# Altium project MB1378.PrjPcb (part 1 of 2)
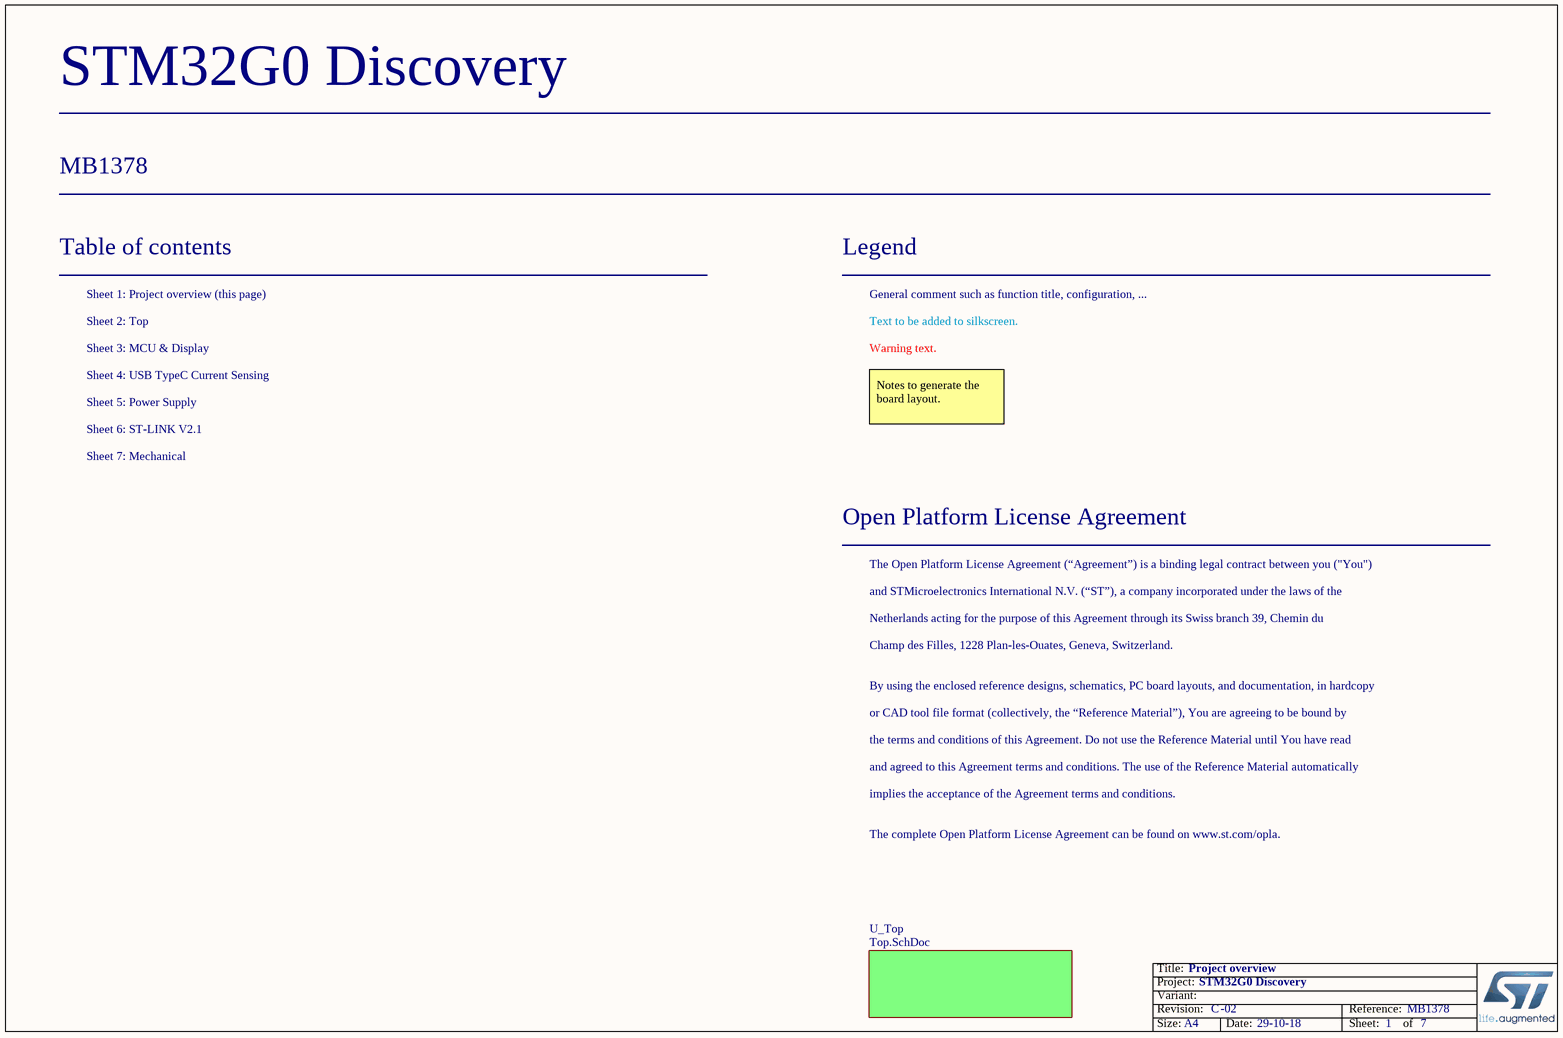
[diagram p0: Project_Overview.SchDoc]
Board_Reference: MB1378; Board_PCB_Revision: C; Board_Name: STM32G0 Discovery; Board_Document_Date: 29-10-18; Board_Assembly_Revision: 02
7 sheets, 200 parts. Net scope: flat (ports and power ports of the same name join across sheets).
Board file: MB1378.PcbDoc
Sheets:
  Project_Overview.SchDoc
    U_Top = Top.SchDoc
      USB Type C = USB_typeC_CurrentSensing.SchDoc
      ST-LINK v2.1 = ST_LINK_V2_1.SchDoc
      STM32G0 MCU and display = MCU_Display.SchDoc
      U_Power_Supply = Power_Supply.SchDoc
      U_Mechanical = Mechanical.SchDoc

## Sheet Project_Overview.SchDoc: Project overview
size A4; Date: Not used; ApprovedBy: Not used; CheckedBy: Not used; Author: Not used; CompanyName: STMicroelectronics; DrawnBy: Not used; Engineer: Not used; Organization: Not used; Address1: Not used; Address2: Not used; Address3: Not used; Address4: Not used; DocumentNumber: 1; Revision: Not used; SheetNumber: 1; SheetTotal: 7

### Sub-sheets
U_Top = Top.SchDoc: no entries

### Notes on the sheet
- Table of contents
- Sheet 1: Project overview (this page)
- Legend
- General comment such as function title, configuration, ...
- Sheet 2: Top
- Sheet 3: MCU & Display
- Sheet 4: USB TypeC Current Sensing
- Text to be added to silkscreen.
- Warning text.
- Sheet 5: Power Supply
- Sheet 6: ST-LINK V2.1
- Notes to generate the board layout.
- Sheet 7: Mechanical
- Open Platform License Agreement
- The Open Platform License Agreement (“Agreement”) is a binding legal contract between you ("You")
- and STMicroelectronics International N.V. (“ST”), a company incorporated under the laws of the
- Netherlands acting for the purpose of this Agreement through its Swiss branch 39, Chemin du
- Champ des Filles, 1228 Plan-les-Ouates, Geneva, Switzerland.
- By using the enclosed reference designs, schematics, PC board layouts, and documentation, in hardcopy
- or CAD tool file format (collectively, the “Reference Material”), You are agreeing to be bound by
- the terms and conditions of this Agreement. Do not use the Reference Material until You have read
- and agreed to this Agreement terms and conditions. The use of the Reference Material automatically
- implies the acceptance of the Agreement terms and conditions.
- The complete Open Platform License Agreement can be found on www.st.com/opla.

## Sheet Top.SchDoc: Top
size A4; Date: Not used; ApprovedBy: Not used; CheckedBy: Not used; Author: Not used; CompanyName: STMicroelectronics; DrawnBy: Not used; Engineer: Not used; Organization: Not used; Address1: Not used; Address2: Not used; Address3: Not used; Address4: Not used; DocumentNumber: 2; Revision: Not used; SheetNumber: 2; SheetTotal: 7
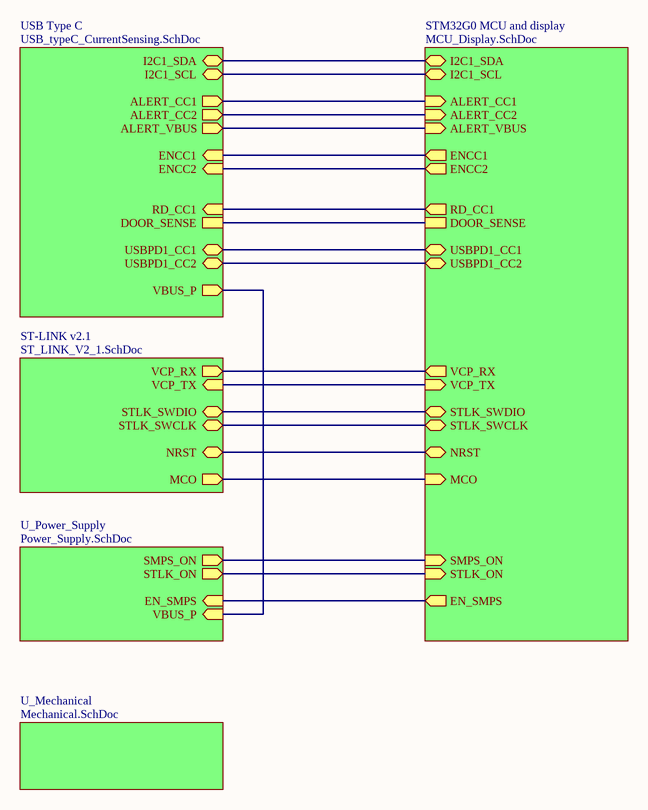
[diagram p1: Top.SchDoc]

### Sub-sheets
ST-LINK v2.1 = ST_LINK_V2_1.SchDoc: NRST (bidir), VCP_RX (out), VCP_TX (in), STLK_SWDIO (bidir), STLK_SWCLK (bidir), MCO (out)
STM32G0 MCU and display = MCU_Display.SchDoc: I2C1_SCL (bidir), I2C1_SDA (bidir), STLK_SWDIO (bidir), STLK_SWCLK (bidir), VCP_RX (out), VCP_TX (in), USBPD1_CC2 (bidir), USBPD1_CC1 (bidir), ENCC2 (out), ENCC1 (out), RD_CC1 (out), ALERT_CC1 (in), ALERT_CC2 (in), ALERT_VBUS (in), EN_SMPS (out), NRST (bidir), MCO (in), SMPS_ON (in), STLK_ON (in), DOOR_SENSE
U_Mechanical = Mechanical.SchDoc: no entries
U_Power_Supply = Power_Supply.SchDoc: SMPS_ON (out), STLK_ON (out), EN_SMPS (in), VBUS_P (in)
USB Type C = USB_typeC_CurrentSensing.SchDoc: I2C1_SDA (bidir), I2C1_SCL (bidir), ALERT_CC1 (out), ALERT_CC2 (out), ALERT_VBUS (out), ENCC2 (in), ENCC1 (in), USBPD1_CC2 (bidir), USBPD1_CC1 (bidir), RD_CC1 (in), VBUS_P (out), DOOR_SENSE

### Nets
(unnamed): sheet USB Type C/I2C1_SDA, sheet STM32G0 MCU and display/I2C1_SDA
(unnamed): sheet USB Type C/I2C1_SCL, sheet STM32G0 MCU and display/I2C1_SCL  [a separate net that carries the same name]
(unnamed): sheet USB Type C/ALERT_CC1, sheet STM32G0 MCU and display/ALERT_CC1  [a separate net that carries the same name]
(unnamed): sheet USB Type C/ALERT_CC2, sheet STM32G0 MCU and display/ALERT_CC2  [a separate net that carries the same name]
(unnamed): sheet USB Type C/ALERT_VBUS, sheet STM32G0 MCU and display/ALERT_VBUS  [a separate net that carries the same name]
(unnamed): sheet USB Type C/ENCC2, sheet STM32G0 MCU and display/ENCC2  [a separate net that carries the same name]
(unnamed): sheet USB Type C/ENCC1, sheet STM32G0 MCU and display/ENCC1  [a separate net that carries the same name]
(unnamed): sheet USB Type C/USBPD1_CC2, sheet STM32G0 MCU and display/USBPD1_CC2  [a separate net that carries the same name]
(unnamed): sheet USB Type C/USBPD1_CC1, sheet STM32G0 MCU and display/USBPD1_CC1  [a separate net that carries the same name]
(unnamed): sheet USB Type C/RD_CC1, sheet STM32G0 MCU and display/RD_CC1  [a separate net that carries the same name]
(unnamed): sheet USB Type C/VBUS_P, sheet U_Power_Supply/VBUS_P  [a separate net that carries the same name]
(unnamed): sheet USB Type C/DOOR_SENSE, sheet STM32G0 MCU and display/DOOR_SENSE  [a separate net that carries the same name]
(unnamed): sheet ST-LINK v2.1/NRST, sheet STM32G0 MCU and display/NRST  [a separate net that carries the same name]
(unnamed): sheet ST-LINK v2.1/VCP_RX, sheet STM32G0 MCU and display/VCP_RX  [a separate net that carries the same name]
(unnamed): sheet ST-LINK v2.1/VCP_TX, sheet STM32G0 MCU and display/VCP_TX  [a separate net that carries the same name]
(unnamed): sheet ST-LINK v2.1/STLK_SWDIO, sheet STM32G0 MCU and display/STLK_SWDIO  [a separate net that carries the same name]
(unnamed): sheet ST-LINK v2.1/STLK_SWCLK, sheet STM32G0 MCU and display/STLK_SWCLK  [a separate net that carries the same name]
(unnamed): sheet ST-LINK v2.1/MCO, sheet STM32G0 MCU and display/MCO  [a separate net that carries the same name]
(unnamed): sheet STM32G0 MCU and display/EN_SMPS, sheet U_Power_Supply/EN_SMPS  [a separate net that carries the same name]
(unnamed): sheet STM32G0 MCU and display/SMPS_ON, sheet U_Power_Supply/SMPS_ON  [a separate net that carries the same name]
(unnamed): sheet STM32G0 MCU and display/STLK_ON, sheet U_Power_Supply/STLK_ON  [a separate net that carries the same name]

## Sheet USB_typeC_CurrentSensing.SchDoc: USB TypeC Current Sensing
size A4; Date: Not used; ApprovedBy: Not used; CheckedBy: Not used; Author: Not used; CompanyName: STMicroelectronics; DrawnBy: Not used; Engineer: Not used; Organization: Not used; Address1: Not used; Address2: Not used; Address3: Not used; Address4: Not used; DocumentNumber: 4; Revision: Not used; SheetNumber: 4; SheetTotal: 7
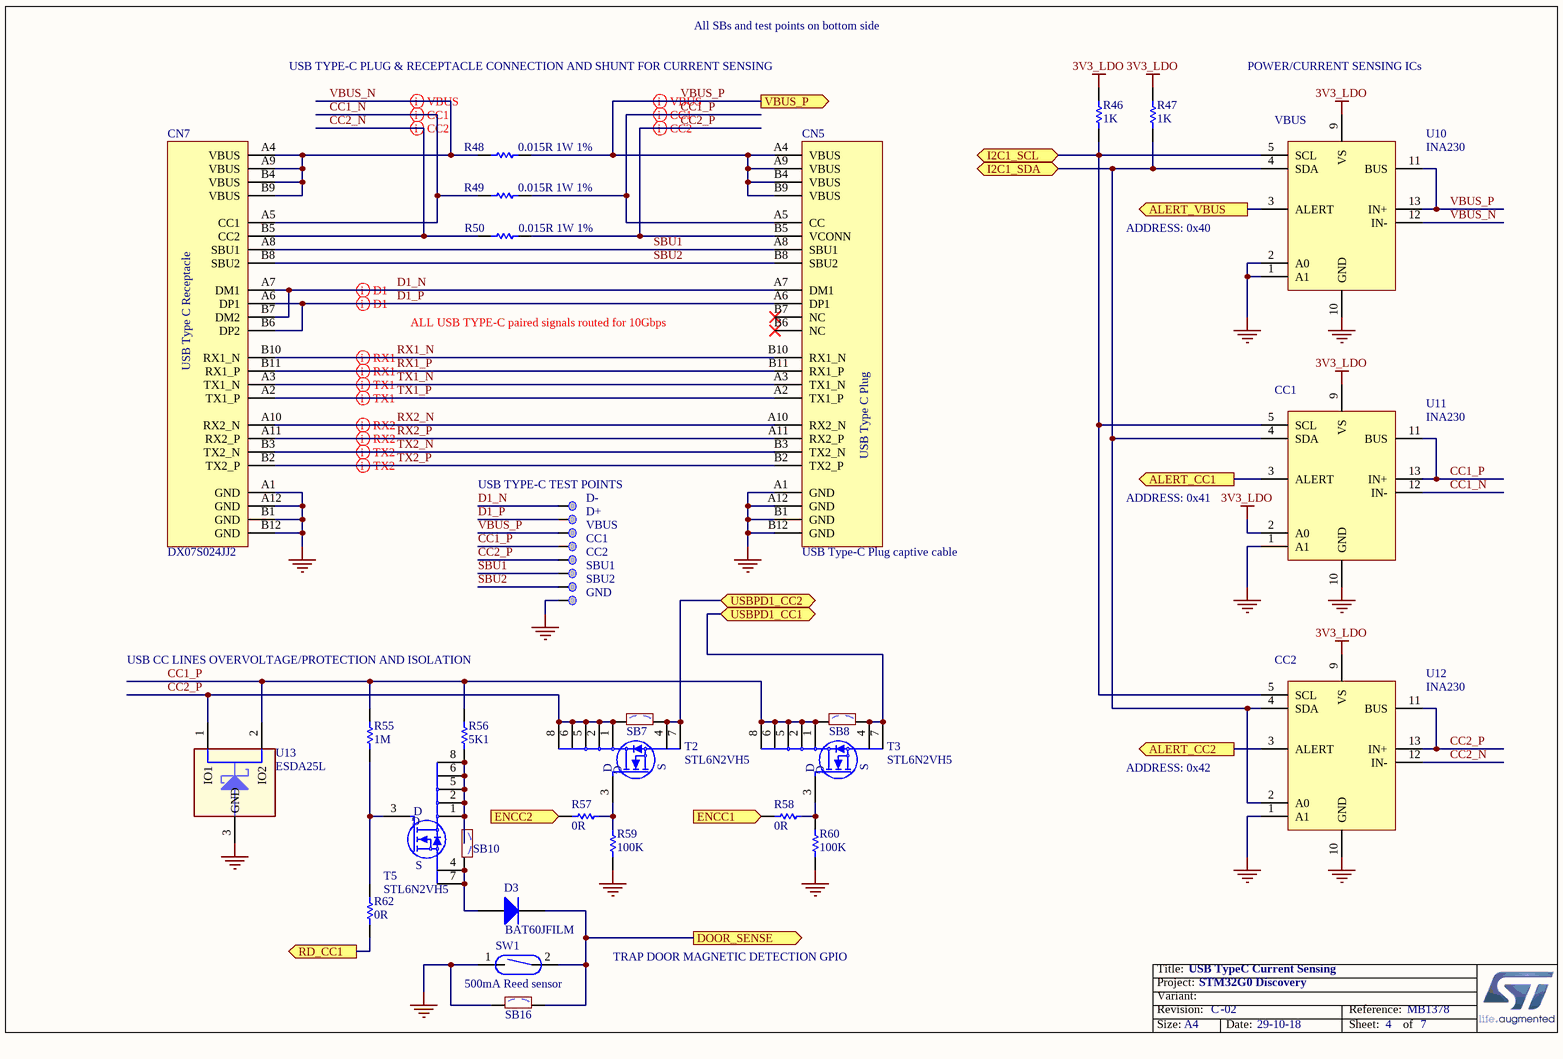
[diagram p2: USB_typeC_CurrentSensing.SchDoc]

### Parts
CC1  Test Point  [TP_SMD_2MM]  (value not drawn)  (no BOM)
CC2  Test Point  [TP_SMD_2MM]  (value not drawn)  (no BOM)
CN5  value USB Type-C Plug captive cable  (hidden comment: USB_TypeC_Plug_DX07P024MJ1)
CN7  value DX07S024JJ2  [CO_JAE_DX07S024JJ2]  (hidden comment: ​Footprint CO_JAE_DX07S024JJ2)
D3  value BAT60JFILM  [DIO_SOD323]
D+  Test Point  [TP_SMD_2MM]  (value not drawn)  (no BOM)
D-  Test Point  [TP_SMD_2MM]  (value not drawn)  (no BOM)
GND  Test Point  [TP_SMD_2MM]  (value not drawn)  (no BOM)
R46  value 1K  [R0603]  (hidden comment: Resistor)
R47  value 1K  [R0603]  (hidden comment: Resistor)
R48  value 0.015R 1W 1%  [RESC3216X06N]  (hidden comment: ​Footprint RESC3216X06N)
R49  value 0.015R 1W 1%  [RESC3216X06N]  (hidden comment: ​Footprint RESC3216X06N)
R50  value 0.015R 1W 1%  [RESC3216X06N]  (hidden comment: ​Footprint RESC3216X06N)
R55  value 1M  [R0603]
R56  value 5K1  [R0402]
R57  value 0R  [R0603]  (hidden comment: Resistor)
R58  value 0R  [R0603]  (hidden comment: Resistor)
R59  value 100K  [R0603]
R60  value 100K  [R0603]
R62  value 0R  [R0603]  (hidden comment: Resistor)
SB7  SB_OFF  [SOLDER-BRIDGE_R0603-0R]  (value not drawn)
SB8  SB_OFF  [SOLDER-BRIDGE_R0603-0R]  (value not drawn)
SB10  SB_OFF  [SOLDER-BRIDGE_R0603-0R]  (value not drawn)
SB16  SB_OFF  [SOLDER-BRIDGE_R0603-0R]  (value not drawn)
SBU1  Test Point  [TP_SMD_2MM]  (value not drawn)  (no BOM)
SBU2  Test Point  [TP_SMD_2MM]  (value not drawn)  (no BOM)
SW1  value 500mA Reed sensor  (hidden comment: SWITCH_CT05)
T2  value STL6N2VH5  [PowerFLAT_2x2]  (hidden comment: ​Footprint PowerFLAT_2x2)
T3  value STL6N2VH5  [PowerFLAT_2x2]  (hidden comment: ​Footprint PowerFLAT_2x2)
T5  value STL6N2VH5  [PowerFLAT_2x2]  (hidden comment: ​Footprint PowerFLAT_2x2)
U10  value INA230  [QFN50P300X300X90-16N-S168]  (hidden comment: ​Footprint QFN50P300X300X90-16N-S168)
U11  value INA230  [QFN50P300X300X90-16N-S168]  (hidden comment: ​Footprint QFN50P300X300X90-16N-S168)
U12  value INA230  [QFN50P300X300X90-16N-S168]  (hidden comment: ​Footprint QFN50P300X300X90-16N-S168)
U13  value ESDA25L  [ESD_SOT23]  (hidden comment: Footprint ESD_SOT23)
VBUS  Test Point  [TP_SMD_2MM]  (value not drawn)  (no BOM)

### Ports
ALERT_CC1 (out), ALERT_CC2 (out), ALERT_VBUS (out), DOOR_SENSE (out), ENCC1 (out), ENCC2 (out), I2C1_SCL (bidir), I2C1_SDA (bidir), RD_CC1 (out), USBPD1_CC1, USBPD1_CC2, VBUS_P (out)

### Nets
3V3_LDO: R46.2 R47.2 U10.9(VS) U11.2(A0) U11.9(VS) U12.9(VS)
GND: CN5.A1(GND) CN5.A12(GND) CN5.B1(GND) CN5.B12(GND) CN7.A1(GND) CN7.A12(GND) CN7.B1(GND) CN7.B12(GND) GND.1 R59.1 R60.1 SB16.1 SW1.1 U10.1(A1) U10.2(A0) U10.10(GND) U11.1(A1) U11.10(GND) U12.1(A1) U12.10(GND) U13.3(GND)
ALERT_CC1: U11.3(ALERT) ; port ALERT_CC1
ALERT_CC2: U12.3(ALERT) ; port ALERT_CC2
ALERT_VBUS: U10.3(ALERT) ; port ALERT_VBUS
CC1_N: CN7.A5(CC1) R49.1 U11.12(IN-)
CC1_P: CC1.1 CN5.A5(CC) R49.2 R55.2 R56.2 SB8.1 T3.1(D) T3.2(D) T3.5(D) T3.6(D) T3.8(D) U11.11(BUS) U11.13(IN+) U13.2(IO2)
CC2_N: CN7.B5(CC2) R50.1 U12.12(IN-)
CC2_P: CC2.1 CN5.B5(VCONN) R50.2 SB7.1 T2.1(D) T2.2(D) T2.5(D) T2.6(D) T2.8(D) U12.11(BUS) U12.13(IN+) U13.1(IO1)
D1_N: CN5.A7(DM1) CN7.A7(DM1) CN7.B7(DM2) D-.1
D1_P: CN5.A6(DP1) CN7.A6(DP1) CN7.B6(DP2) D+.1
DOOR_SENSE: D3.2(K) SB16.2 SW1.2 ; port DOOR_SENSE
ENCC1: R58.2 ; port ENCC1
ENCC2: R57.2 ; port ENCC2
I2C1_SCL: R46.1 U10.5(SCL) U11.5(SCL) U12.5(SCL) ; port I2C1_SCL
I2C1_SDA: R47.1 U10.4(SDA) U11.4(SDA) U12.2(A0) U12.4(SDA) ; port I2C1_SDA
RD_CC1: R62.1 ; port RD_CC1
RX1_N: CN5.B10(RX1_N) CN7.B10(RX1_N)
RX1_P: CN5.B11(RX1_P) CN7.B11(RX1_P)
RX2_N: CN5.A10(RX2_N) CN7.A10(RX2_N)
RX2_P: CN5.A11(RX2_P) CN7.A11(RX2_P)
SBU1: CN5.A8(SBU1) CN7.A8(SBU1) SBU1.1
SBU2: CN5.B8(SBU2) CN7.B8(SBU2) SBU2.1
TX1_N: CN5.A3(TX1_N) CN7.A3(TX1_N)
TX1_P: CN5.A2(TX1_P) CN7.A2(TX1_P)
TX2_N: CN5.B3(TX2_N) CN7.B3(TX2_N)
TX2_P: CN5.B2(TX2_P) CN7.B2(TX2_P)
USBPD1_CC1: SB8.2 T3.4(S) T3.7(S) ; port USBPD1_CC1
USBPD1_CC2: SB7.2 T2.4(S) T2.7(S) ; port USBPD1_CC2
VBUS_N: CN7.A4(VBUS) CN7.A9(VBUS) CN7.B4(VBUS) CN7.B9(VBUS) R48.1 U10.12(IN-)
VBUS_P: CN5.A4(VBUS) CN5.A9(VBUS) CN5.B4(VBUS) CN5.B9(VBUS) R48.2 U10.11(BUS) U10.13(IN+) VBUS.1 ; port VBUS_P
NetD3_1: D3.1(A) SB10.2 T5.4(S) T5.7(S)
NetR55_1: R55.1 R62.2 T5.3(G)
NetR56_1: R56.1 SB10.1 T5.1(D) T5.2(D) T5.5(D) T5.6(D) T5.8(D)
NetR57_1: R57.1 R59.2 T2.3(G)
NetR58_1: R58.1 R60.2 T3.3(G)

Not connected (* = marked no-connect by the designer): CN5 B6(NC)* B7(NC)*; U10 6(NC) 7(NC) 8(NC) 14(NC) 15(NC) 16(NC); U11 6(NC) 7(NC) 8(NC) 14(NC) 15(NC) 16(NC); U12 6(NC) 7(NC) 8(NC) 14(NC) 15(NC) 16(NC)

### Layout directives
differential pair: CC1_N, CC1_P, CC2_N, CC2_P, D1_N, D1_P, RX1_N, RX1_P, RX2_N, RX2_P, TX1_N, TX1_P, TX2_N, TX2_P, VBUS_N, VBUS_P

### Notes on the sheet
- All SBs and test points on bottom side
- USB TYPE-C PLUG & RECEPTACLE CONNECTION AND SHUNT FOR CURRENT SENSING
- POWER/CURRENT SENSING ICs
- (near U10) VBUS
- ADDRESS: 0x40
- ALL USB TYPE-C paired signals routed for 10Gbps
- (near U11) CC1
- (near D-) USB TYPE-C TEST POINTS
- ADDRESS: 0x41
- USB CC LINES OVERVOLTAGE/PROTECTION AND ISOLATION
- (near U12) CC2
- ADDRESS: 0x42
- TRAP DOOR MAGNETIC DETECTION GPIO

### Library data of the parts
CC1 CC2 D+ D- GND SBU1 SBU2 VBUS = MCD-00177: Test Point 2mm; Part_Type: Mechanical; Initial_Board_Reference: MB1274
CN5 = MCD-01383: Connector, USB TYpe-C Plug cable interface to PCB with specific layout; Manufacturer_Part_Number: TBD (custom-made connector); Manufacturer: ADVANCED-CONNECTEK (KSN) INC.; Provided_By: Subcon; Initial_Board_Reference: MB1378; Remark: Footprint to be created
CN7 = MCD-01022: USB Type-C connector DX07 Series RECEPTACLE; Manufacturer: JAE; Provided_By: Subcon; Initial_Board_Reference: MB1378
D3 = MCD-00034: BAT60JFILM; Manufacturer: STMICROELECTRONICS; Part_Type: Diode; ECCN_US: EAR99; ECCN_EU: NEC; Provided_By: Subcon; Initial_Board_Reference: MB1274
R46 R47 = MCD-00070: Resistor,1K,0603,1%,1/10W; Manufacturer_Part_Number: RC0603FR-071KL; Manufacturer: YAGEO; Provided_By: SUBCO; Initial_Board_Reference: MB1274; Path: ws/MCD_ApplicationBoards/Lists/MCDPARTSdatabase; Item Type: Item
R48-R50 = MCD-01029: 0.015 Ohm 1W 1% 1206 Shunt resistor for current sensing; Manufacturer_Part_Number: ERJ8CWFR015V; Manufacturer: PANASONIC; Provided_By: Subcon; Initial_Board_Reference: MB1378
R55 = MCD-00257: Resistor,1M,0603,1%,1/10W; Manufacturer_Part_Number: RC0603FR-071ML; Manufacturer: YAGEO; Provided_By: Subcon; Initial_Board_Reference: MB1319
R56 = MCD-00333: Resistor,5K1,0402,1%,1/16W; Manufacturer_Part_Number: RC0402FR-075K1L; Manufacturer: YAGEO; Provided_By: Subcon; Initial_Board_Reference: MB1272
R57 R58 R62 = MCD-00056: Resistor,0R,0603,5%,1/10W; Manufacturer_Part_Number: RC0603JR-070RL; Manufacturer: YAGEO; Provided_By: subcon; Initial_Board_Reference: MB1274
R59 R60 = MCD-00223: Resistor,100K,0603,1%,1/10W; Manufacturer_Part_Number: RC0603FR-07100KL; Manufacturer: YAGEO; Provided_By: Subcon; Initial_Board_Reference: MB1319
SB7 SB8 SB10 = MCD-00072: Solder Bridge OFF; Part_Type: Mechanical; Initial_Board_Reference: MB1274
SB16 = MCD-00072: Solder Bridge OFF; Part_Type: Mechanical; Manufacturer_Part_Number: RC0603JR-070RL; Manufacturer: YAGEO; Provided_By: SUBCO; Initial_Board_Reference: MB1274; Path: ws/MCD_ApplicationBoards/Lists/MCDPARTSdatabase; Item Type: Item
SW1 = MCD-01373: Reed switch, CT05 series, SPST-NO, CMS, 500mA, 140Vdc, 5W; Part_Type: Misc; Manufacturer_Part_Number: CT05-G1; Manufacturer: COTO TECHNOLOGY; Provided_By: Subcon; Initial_Board_Reference: MB1378
T2 T3 T5 = MCD-01028: N-channel 20 V, 0.025 Ω typ., 6 A STripFET™ V Power MOSFET in a PowerFLAT™ 2x2 package; Part_Type: IC; Manufacturer: STMICROELECTRONICS; ECCN_US: EAR99; ECCN_EU: NEC; Provided_By: STM; Initial_Board_Reference: MB1378
U10-U12 = MCD-01017: Texas Intruments High- or Low-Side Measurement, Bidirectional CURRENT/POWER MONITOR with I2C™ Interface; Part_Type: IC; Manufacturer: TI; ECCN_US: EAR99; ECCN_EU: NEC; Provided_By: Subcon; Initial_Board_Reference: MB1378
U13 = MCD-01027: DUAL TRANSIL ARRAY FOR ESD PROTECTION; Part_Type: Diode; Manufacturer: STMICROELECTRONICS; ECCN_US: EAR99; ECCN_EU: NEC; Provided_By: STM; Initial_Board_Reference: MB1378

## Sheet ST_LINK_V2_1.SchDoc: ST-LINK V2.1
size A4; Date: Not used; ApprovedBy: Not used; CheckedBy: Not used; Author: Not used; CompanyName: STMicroelectronics; DrawnBy: Not used; Engineer: Not used; Organization: Not used; Address1: Not used; Address2: Not used; Address3: Not used; Address4: Not used; DocumentNumber: 6; Revision: Not used; SheetNumber: 6; SheetTotal: 7
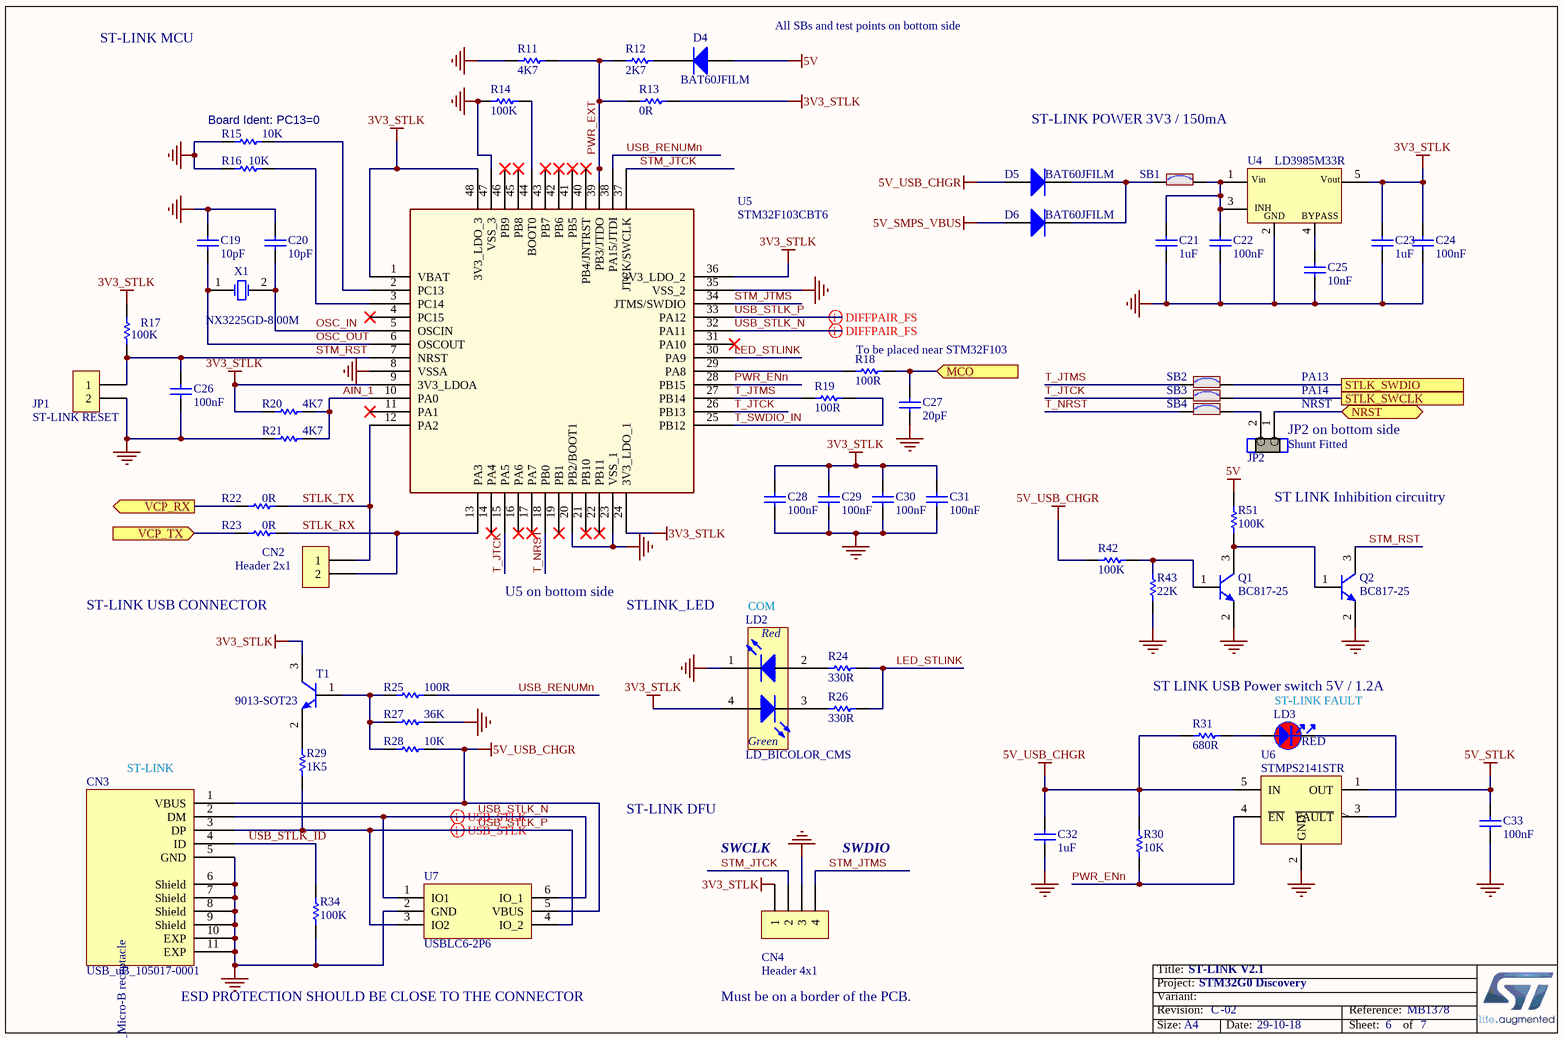
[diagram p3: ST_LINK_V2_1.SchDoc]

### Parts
C19  value 10pF  [C0402]
C20  value 10pF  [C0402]
C21  value 1uF  [C0603]
C22  value 100nF  [C0402]
C23  value 1uF  [C0603]
C24  value 100nF  [C0402]
C25  value 10nF  [C0402]
C26  value 100nF  [C0402]
C27  value 20pF  [C0603]  (hidden comment: Capacitor)
C28  value 100nF  [C0402]
C29  value 100nF  [C0402]
C30  value 100nF  [C0402]
C31  value 100nF  [C0402]
C32  value 1uF  [C0603]
C33  value 100nF  [C0402]
CN2  value Header 2x1  [CON_SAMTEC_TSW-102-07-G-S]
CN3  value USB_uB_105017-0001  [CON_USBMICROB_MOLEX_105017-0001_H2P90]
CN4  value Header 4x1  [CON_SAMTEC_TSW-104-07-G-S]
D4  value BAT60JFILM  [DIO_SOD323]
D5  value BAT60JFILM  [DIO_SOD323]
D6  value BAT60JFILM  [DIO_SOD323]
JP1  value ST-LINK RESET  [CON_SAMTEC_TSW-102-07-G-S]
JP2  value Shunt Fitted  [CON_WP_707-2-02-2-20-00]  (hidden comment: Jumper_Header1.27 2x1 Fitted)
LD2  value LD_BICOLOR_CMS  [LED_BI-GR_HSMF-A201-A00J1]
LD3  value RED  [LED_0603_VISHAY_VLMS1300-GS08_RED_1A2K_H0P8]  (hidden comment: LED_red)
Q1  value BC817-25  [NPN_SOT23]  (hidden comment: 9013-SOT23)
Q2  value BC817-25  [NPN_SOT23]  (hidden comment: 9013-SOT23)
R11  value 4K7  [R0402]
R12  value 2K7  [R0402]
R13  value 0R  [R0402]
R14  value 100K  [R0402]
R15  value 10K  [R0402]
R16  value 10K  [R0402]
R17  value 100K  [R0402]
R18  value 100R  [R0603]  (hidden comment: Resistor)
R19  value 100R  [R0402]
R20  value 4K7  [R0402]
R21  value 4K7  [R0402]
R22  value 0R  [R0402]
R23  value 0R  [R0402]
R24  value 330R  [R0402]
R25  value 100R  [R0402]
R26  value 330R  [R0402]
R27  value 36K  [R0402]
R28  value 10K  [R0402]
R29  value 1K5  [R0402]
R30  value 10K  [R0402]
R31  value 680R  [R0603]  (hidden comment: Resistor)
R34  value 100K  [R0402]
R42  value 100K  [R0603]  (hidden comment: Resistor)
R43  value 22K  [R0603]  (hidden comment: Resistor)
R51  value 100K  [R0603]  (hidden comment: Resistor)
SB1  (no value)  [SOLDER-BRIDGE_R0603-0R]
SB2  (no value)  [SOLDER-BRIDGE_R0603-0R]
SB3  (no value)  [SOLDER-BRIDGE_R0603-0R]
SB4  (no value)  [SOLDER-BRIDGE_R0603-0R]
T1  value 9013-SOT23  [NPN_SOT23]
U4  value LD3985M33R  [REG_SOT23-5L]
U5  value STM32F103CBT6  [ICC_LQFP48_7X7_P050]
U6  STMPS2141STR  [MOS_SOT23-5L]
U7  value USBLC6-2P6  [ESD_SOT666]
X1  value NX3225GD-8.00M  [CRY_NX3225GD_2P]

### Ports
MCO (in), NRST (bidir), STLK_SWCLK, STLK_SWDIO, VCP_RX (out), VCP_TX (in)

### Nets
3V3_STLK: C23.2 C24.2 C28.2 C29.2 C30.2 C31.2 CN4.1 LD2.4(YellowGreen_anode) R13.2 R17.2 R20.1 T1.3(C) U4.5(Vout) U5.1(VBAT) U5.9(3V3_LDOA) U5.24(3V3_LDO_1) U5.36(3V3_LDO_2) U5.48(3V3_LDO_3)
5V: D4.1(A) R51.2
5V_SMPS_VBUS: D6.1(A)
5V_STLK: C33.2 U6.1(OUT)
5V_USB_CHGR: C32.2 CN3.1(VBUS) D5.1(A) R28.1 R30.2 R31.1 R42.1 U6.5(IN) U7.5(VBUS)
GND: C19.2 C20.2 C21.2 C22.1 C23.1 C24.1 C25.1 C26.1 C27.1 C28.1 C29.1 C30.1 C31.1 C32.1 C33.1 CN3.5(GND) CN3.6(Shield) CN3.7(Shield) CN3.8(Shield) CN3.9(Shield) CN3.10(EXP) CN3.11(EXP) CN4.3 JP1.2 LD2.1(RED_cathode) Q1.2(E) Q2.2(E) R11.1 R14.1 R15.2 R16.1 R21.1 R27.1 R34.1 R43.1 U4.2(GND) U5.8(VSSA) U5.20(PB2/BOOT1) U5.23(VSS_1) U5.35(VSS_2) U5.47(VSS_3) U6.2(GND) U7.2(GND)
AIN_1: R20.2 R21.2 U5.10(PA0)
LED_STLINK: R24.2 R26.2 U5.30(PA9)
MCO: C27.2 R18.2 ; port MCO
NRST: JP2.1 ; port NRST
OSC_IN: C20.1 U5.5(OSCIN) X1.2(OSC2)
OSC_OUT: C19.1 U5.6(OSCOUT) X1.1(OSC1)
PWR_ENn: R30.1 U5.28(PB15) U6.4(~{EN})
PWR_EXT: R11.2 R12.1 R13.1 U5.39(PB3/JTDO)
STLK_RX: CN2.2 R23.2 U5.13(PA3)
STLK_SWCLK: SB3.2 ; port STLK_SWCLK
STLK_SWDIO: SB2.2 ; port STLK_SWDIO
STLK_TX: CN2.1 R22.1 U5.12(PA2)
STM_JTCK: CN4.2 U5.37(JTCK/SWCLK)
STM_JTMS: CN4.4 U5.34(JTMS/SWDIO)
STM_RST: C26.2 JP1.1 Q2.3(C) R17.1 U5.7(NRST)
T_JTCK: SB3.1 U5.15(PA5) U5.26(PB13)
T_JTMS: R19.1 SB2.1 U5.27(PB14)
T_NRST: SB4.1 U5.18(PB0)
T_SWDIO_IN: R19.2 U5.25(PB12)
USB_RENUMn: R25.2 U5.38(PA15/JTDI)
USB_STLK_ID: CN3.4(ID) R34.2
USB_STLK_N: CN3.2(DM) U5.32(PA11) U7.1(IO1) U7.6(IO_1)
USB_STLK_P: CN3.3(DP) R29.1 U5.33(PA12) U7.3(IO2) U7.4(IO_2)
VCP_RX: R22.2 ; port VCP_RX
VCP_TX: R23.1 ; port VCP_TX
NetC21_1: C21.1 C22.2 SB1.2 U4.1(Vin) U4.3(CE)
NetC25_2: C25.2 U4.4(BYPASS)
NetD4_2: D4.2(K) R12.2
NetD5_2: D5.2(K) D6.2(K) SB1.1
NetJP2_2: JP2.2 SB4.2
NetLD2_2: LD2.2(Red_anode) R24.1
NetLD2_3: LD2.3(YellowGreen_cathode) R26.1
NetLD3_1: LD3.1 R31.2
NetLD3_2: LD3.2 U6.3(~{FAULT})
NetQ1_1: Q1.1(B) R42.2 R43.2
NetQ1_3: Q1.3(C) Q2.1(B) R51.1
NetR14_2: R14.2 U5.44(BOOT0)
NetR15_1: R15.1 U5.2(PC13)
NetR16_2: R16.2 U5.3(PC14)
NetR18_1: R18.1 U5.29(PA8)
NetR25_1: R25.1 R27.2 R28.2 T1.1(B)
NetR29_2: R29.2 T1.2(E)

Not connected (* = marked no-connect by the designer): U5 4(PC15)* 11(PA1)* 14(PA4)* 16(PA6)* 17(PA7)* 19(PB1)* 21(PB10)* 22(PB11)* 31(PA10)* 40(PB4/JNTRST)* 41(PB5)* 42(PB6)* 43(PB7)* 45(PB8)* 46(PB9)*

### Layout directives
differential pair: USB_STLK_N, USB_STLK_P

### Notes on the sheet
- ST-LINK MCU
- All SBs and test points on bottom side
- (near R15) Board Ident: PC13=0
- ST-LINK POWER 3V3 / 150mA
- (near R18) To be placed near STM32F103
- PA13
- (near JP2) JP2 on bottom side
- (near JP2) PA14
- (near JP2) NRST
- ST LINK Inhibition circuitry
- ST-LINK USB CONNECTOR
- U5 on bottom side
- STLINK_LED
- COM
- ST LINK USB Power switch 5V / 1.2A
- (near LD3) ST-LINK FAULT
- (near CN3) ST-LINK
- ST-LINK DFU
- SWCLK
- SWDIO
- (near CN3) ESD PROTECTION SHOULD BE CLOSE TO THE CONNECTOR
- Must be on a border of the PCB.

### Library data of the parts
C19 C20 = MCD-00015: Capacitor, MLCC, 10pF, 50V, NPO, 5%, 0402, T=0,5mm; Manufacturer_Part_Number: CC0402JRNPO9BN100; Manufacturer: YAGEO; Provided_By: subcon; Initial_Board_Reference: MB1274
C21 C23 C32 = MCD-00238: Capacitor, MLCC, 1uF, 6V3, X5R, 10%, 0603, T=0,8mm; Manufacturer_Part_Number: CC0603KRX5R5BB105; Manufacturer: YAGEO; Provided_By: Subcon; Initial_Board_Reference: MB1319
C22 C24 C26 C28-C31 C33 = MCD-00006: Capacitor, MLCC, 100nF, 16V, X7R, 10%, 0402, T=0.5mm; Manufacturer_Part_Number: CC0402KRX7R7BB104; Manufacturer: YAGEO; Provided_By: Subcon; Initial_Board_Reference: MB1274
C25 = MCD-00011: Capacitor, MLCC, 10nF, 16V, X7R, 10%, 0402, T=0.5mm; Manufacturer_Part_Number: CC0402KRX7R7BB103; Manufacturer: YAGEO; Provided_By: Subcon; Initial_Board_Reference: MB1274
C27 = MCD-00638: Capacitor, MLCC, 20pF, 50V, NPO, 5%, 0603, T=0,8mm; Manufacturer_Part_Number: CC0603JRNPO9BN200; Manufacturer: YAGEO; Provided_By: Subcon; Initial_Board_Reference: MB1319
CN2 JP1 = MCD-00032: Header, 2x1, 2,54mm, VR, TH, Height 5.84mm/2.54mm; Manufacturer_Part_Number: TSW-102-07-x-S; Manufacturer: SAMTEC; Part_Type: Connector; Provided_By: Subcon; Initial_Board_Reference: MB1274
CN3 = MCD-00028: USB-MICRO-B, 0.65mm, RA, SMT, Bottom Mount,; Manufacturer_Part_Number: 1050170001; Manufacturer: MOLEX; Part_Type: Connector; Provided_By: Subcon; Initial_Board_Reference: MB1274
CN4 = MCD-00029: Header, 4x1, 2,54mm, VR, TH, Height 5.84mm/2.54mm; Manufacturer_Part_Number: TSW-104-07-x-S; Manufacturer: SAMTEC; Part_Type: Connector; Provided_By: Subcon; Initial_Board_Reference: MB1274
D4-D6 = MCD-00034: as D3 on sheet USB_typeC_CurrentSensing
JP2 = MCD-01428: Header, 2x1, 1,27mm, Right Angled, Single Row, Height 3.05mm/1.27mm; Part_Type: Connector; Manufacturer_Part_Number: 707-2-02-2-20-00; Manufacturer: W & P Products; Provided_By: SUBCO; Initial_Board_Reference: MB1441; Path: ws/MCD_ApplicationBoards/Lists/MCDPARTSdatabase; Item Type: Item
LD2 = MCD-00051: LED Bicolor; Manufacturer_Part_Number: HSMF-A201-A00J1; Manufacturer: AVAGO TECHNOLOGIES; Alternate_Manufacturer_Part_Number: LE-RGW35280; Alternate_Manufacturer: EVERLUCK; Part_Type: Display; ECCN_US: EAR99; ECCN_EU: NEC; Provided_By: Subcon; Initial_Board_Reference: MB1274
LD3 = MCD-00587: LED Red, 0603 SMD, 2V Forward Voltage; Part_Type: Display; Manufacturer_Part_Number: VLMS1300-GS08; Manufacturer: VISHAY; Alternate_Manufacturer_Part_Number: LS Q976-NR-1; Alternate_Manufacturer: OSRAM OPTO SEMICONDUCTORS; Provided_By: Subcon; Initial_Board_Reference: MB1331
Q1 Q2 = MCD-01385: Transistor Bipolar NPN, 45V, 500mA, 100MHz, 300mW, SOT23-3; Part_Type: IC; Manufacturer_Part_Number: BC817-25LT3G; Manufacturer: ON SEMICONDUCTOR; Provided_By: Subcon; Initial_Board_Reference: MB1378
R11 R20 R21 = MCD-00065: Resistor,4K7,0402,1%,1/16W; Manufacturer_Part_Number: RC0402FR-074K7L; Manufacturer: YAGEO; Alternate_Manufacturer_Part_Number: RT0402FRE074K7L; Provided_By: Subcon; Initial_Board_Reference: MB1274
R12 = MCD-00055: Resistor,2K7,0402,1%,1/16W; Manufacturer_Part_Number: RC0402FR-072K7L; Manufacturer: YAGEO; Provided_By: Subcon; Initial_Board_Reference: MB1274
R13 R22 R23 = MCD-00052: Resistor,0R,0402,5%,1/16W; Manufacturer_Part_Number: RC0402JR-070RL; Manufacturer: YAGEO; Provided_By: Subcon; Initial_Board_Reference: MB1274
R14 R17 R34 = MCD-00059: Resistor,100K,0402,1%,1/16W; Manufacturer_Part_Number: RC0402FR-07100KL; Manufacturer: YAGEO; Alternate_Manufacturer_Part_Number: RT0402FRE07100KL; Provided_By: Subcon; Initial_Board_Reference: MB1274
R15 R16 R28 R30 = MCD-00053: Resistor,10K,0402,1%,1/16W; Manufacturer_Part_Number: RC0402FR-0710KL; Manufacturer: YAGEO; Provided_By: subcon; Initial_Board_Reference: MB1274
R18 = MCD-00224: Resistor,100R,0603,1%,1/10W; Manufacturer_Part_Number: RC0603FR-07100RL; Manufacturer: YAGEO; Provided_By: Subcon; Initial_Board_Reference: MB1319
R19 R25 = MCD-00067: Resistor,100R,0402,1%,1/16W; Manufacturer_Part_Number: RC0402FR-07100RL; Manufacturer: YAGEO; Provided_By: Subcon; Initial_Board_Reference: MB1274
R24 R26 = MCD-00062: Resistor,330R,0402,1%,1/16W; Manufacturer_Part_Number: RC0402FR-07330RL; Manufacturer: YAGEO; Provided_By: Subcon; Initial_Board_Reference: MB1274
R27 = MCD-00069: Resistor,36K,0402,1%,1/16W; Manufacturer_Part_Number: RC0402FR-0736KL; Manufacturer: YAGEO; Provided_By: Subcon; Initial_Board_Reference: MB1274
R29 = MCD-00068: Resistor,1K5,0402,1%,1/16W; Manufacturer_Part_Number: RC0402FR-071K5L; Manufacturer: YAGEO; Provided_By: Subcon; Initial_Board_Reference: MB1274
R31 = MCD-00508: Resistor,680R,0603,1%,1/10W; Manufacturer_Part_Number: RC0603FR-07680RL; Manufacturer: YAGEO; Provided_By: Subcon
R42 R51 = MCD-00223: Resistor,100K,0603,1%,1/10W; Manufacturer_Part_Number: RC0603FR-07100KL; Manufacturer: YAGEO; Provided_By: SUBCO; Initial_Board_Reference: MB1319; Path: ws/MCD_ApplicationBoards/Lists/MCDPARTSdatabase; Item Type: Item
R43 = MCD-00430: Resistor,22K,0603,1%,1/10W; Manufacturer_Part_Number: RC0603FR-0722KL; Manufacturer: YAGEO; Provided_By: Subcon
SB1-SB4 = MCD-00071: Solder Bridge ON; Part_Type: Mechanical; Provided_By: Subcon; Initial_Board_Reference: MB1274
T1 = MCD-00073: NPN Bipolar Transistor; Manufacturer_Part_Number: BSR14; Manufacturer: NXP; Part_Type: IC; ECCN_US: EAR99; ECCN_EU: NEC; Provided_By: Subcon; Initial_Board_Reference: MB1274
U4 = MCD-00086: Ultra low drop-low noise BiCMOS voltage, regulators low ESR capacitors compatible; Manufacturer: STMICROELECTRONICS; Part_Type: IC; ECCN_US: EAR99; ECCN_EU: NEC; Provided_By: Subcon; Initial_Board_Reference: MB1274
U5 = MCD-00085: Medium-density performance line ARM-based 32-bit MCU with 128KB Flash; Manufacturer: STMICROELECTRONICS; Part_Type: IC; ECCN_US: 3A991A2; ECCN_EU: NEC; Provided_By: Subcon; Initial_Board_Reference: MB1274
U6 = MCD-00083: Enhanced single channel power switches with active low enable pin; Part_Type: IC; Manufacturer: STMICROELECTRONICS; Alternate_Manufacturer_Part_Number: TPS2041C; Alternate_Manufacturer: TEXAS INSTRUMENTS; Provided_By: Subcon; Initial_Board_Reference: MB1274
U7 = MCD-00169: USB OTG FS ESD protection; Manufacturer: STMICROELECTRONICS; Part_Type: IC; Provided_By: Subcon; ECCN_US: EAR99; ECCN_EU: NEC; Initial_Board_Reference: MB1274
X1 = MCD-00092: Crystal 8Mhz, 8pF, -+50PPM, SMD; Manufacturer_Part_Number: NX3225GD 8MHz EXS00A-CG04874; Manufacturer: NDK; Part_Type: Crystal_Osc; ECCN_US: EAR99; ECCN_EU: NEC; Provided_By: STM; Initial_Board_Reference: MB1274

## Sheet MCU_Display.SchDoc: MCU & Display
size A4; Date: Not used; ApprovedBy: Not used; CheckedBy: Not used; Author: Not used; CompanyName: STMicroelectronics; DrawnBy: Not used; Engineer: Not used; Organization: Not used; Address1: Not used; Address2: Not used; Address3: Not used; Address4: Not used; DocumentNumber: 3; Revision: Not used; SheetNumber: 3; SheetTotal: 7
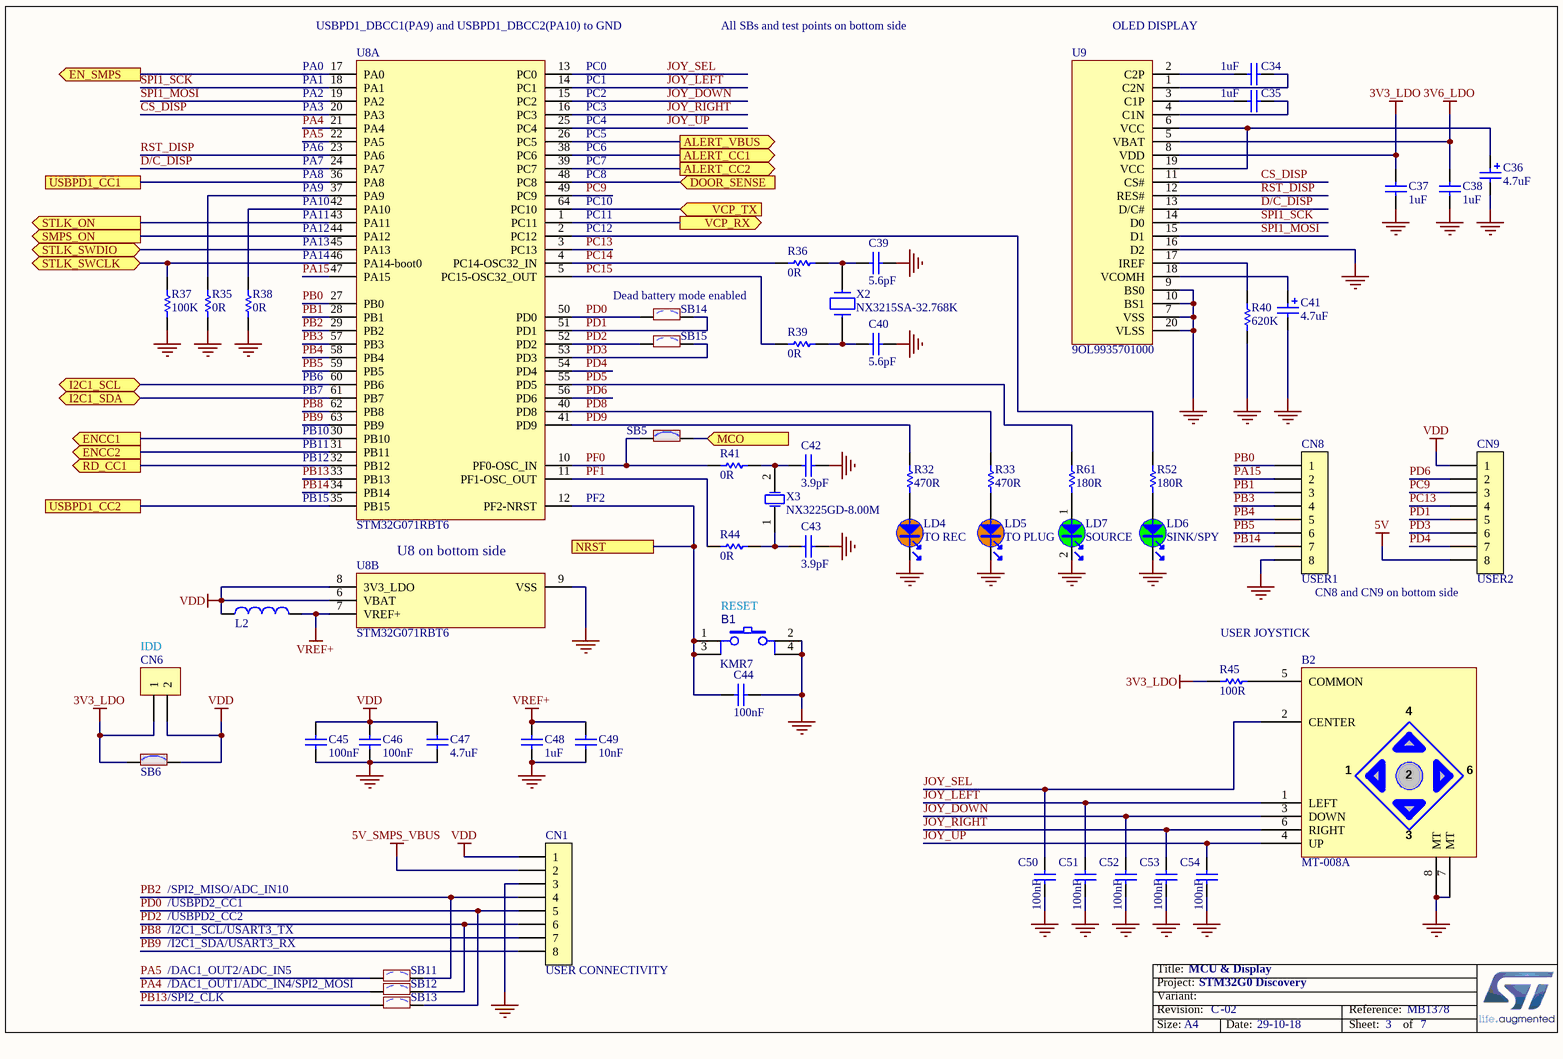
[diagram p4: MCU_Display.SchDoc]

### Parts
B1  value KMR7  [SWI_C&K_KMR721NG-LFS]  (hidden comment: SW-PUSH-CMS_KMR_NG)
B2  value MT-008A  [SWI_XIEJIA_MT-008A_6P]
C34  value 1uF  [C0603]
C35  value 1uF  [C0603]
C36  value 4.7uF  [CPOL_TAJ-A_1206_H180]  (hidden comment: ​Footprint CPOL_TAJ-A_1206_H180)
C37  value 1uF  [C0603]
C38  value 1uF  [C0603]
C39  value 5.6pF  [C0402]  (hidden comment: Capacitor)
C40  value 5.6pF  [C0402]  (hidden comment: Capacitor)
C41  value 4.7uF  [CPOL_TAJ-A_1206_H180]  (hidden comment: ​Footprint CPOL_TAJ-A_1206_H180)
C42  value 3.9pF  [C0402]
C43  value 3.9pF  [C0402]
C44  value 100nF  [C0402]
C45  value 100nF  [C0402]
C46  value 100nF  [C0402]
C47  value 4.7uF  [C0603]  (hidden comment: Capacitor)
C48  value 1uF  [C0603]  (hidden comment: Capacitor)
C49  value 10nF  [C0603]
C50  value 100nF  [C0402]
C51  value 100nF  [C0402]
C52  value 100nF  [C0402]
C53  value 100nF  [C0402]
C54  value 100nF  [C0402]
CN1  value USER CONNECTIVITY  [CO_SAMTEC_TSW-109-08-X-S-RA]  (hidden comment: Header 8x1)
CN6  (no value)  [CON_988-JIUBABA_PHFS25-11-02-G0B115-T-1]
CN8  value USER1  [CON_SAMTEC_TSW-108-07-X-S]  (hidden comment: Header 8x1)
CN9  value USER2  [CON_SAMTEC_TSW-108-07-X-S]  (hidden comment: Header 8x1)
L2  (no value)  [L0603]
LD4  value TO REC  [LED_BROADCOM-HSML-C120]  (hidden comment: LED_orange)
LD5  value TO PLUG  [LED_BROADCOM-HSML-C120]  (hidden comment: LED_orange)
LD6  value SINK/SPY  [LED_BROADCOM-HSMG-C120]  (hidden comment: LED_green)
LD7  value SOURCE  [LED_BROADCOM-HSMG-C120]  (hidden comment: LED_green)
R32  value 470R  [R0603]  (hidden comment: Resistor)
R33  value 470R  [R0603]  (hidden comment: Resistor)
R35  value 0R  [R0603]
R36  value 0R  [R0603]
R37  value 100K  [R0603]
R38  value 0R  [R0603]
R39  value 0R  [R0603]
R40  value 620K  [R0603]
R41  value 0R  [R0603]
R44  value 0R  [R0603]
R45  value 100R  [R0603]
R52  value 180R  [R0603]  (hidden comment: Resistor)
R61  value 180R  [R0603]  (hidden comment: Resistor)
SB5  (no value)  [SOLDER-BRIDGE_R0603-0R]
SB6  (no value)  [SOLDER-BRIDGE_R0603-0R]
SB11  SB_OFF  [SOLDER-BRIDGE_R0603-0R]  (value not drawn)
SB12  SB_OFF  [SOLDER-BRIDGE_R0603-0R]  (value not drawn)
SB13  SB_OFF  [SOLDER-BRIDGE_R0603-0R]  (value not drawn)
SB14  SB_OFF  [SOLDER-BRIDGE_R0603-0R]  (value not drawn)
SB15  SB_OFF  [SOLDER-BRIDGE_R0603-0R]  (value not drawn)
U8  value STM32G071RBT6  [TSQFP50P1200X1200X160-64N]  (hidden comment: ​Footprint TSQFP50P1200X1200X160-64N)  (parts A,B of 2)
U9  value 9OL9935701000  [OLED_RITDISPLAY_9OL9935701000-MB1378B-01]  (hidden comment: OLED_RITDISPLAY_9OL9935701000)
X2  value NX3215SA-32.768K  [CRY_NX3215SA_2P]
X3  value NX3225GD-8.00M  [CRY_NX3225GD_2P]

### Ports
ALERT_CC1 (out), ALERT_CC2 (out), ALERT_VBUS (out), DOOR_SENSE (in), EN_SMPS (out), ENCC1 (out), ENCC2 (out), I2C1_SCL (bidir), I2C1_SDA (bidir), MCO (in), NRST, RD_CC1 (out), SMPS_ON (out), STLK_ON (out), STLK_SWCLK (bidir), STLK_SWDIO (bidir), USBPD1_CC1, USBPD1_CC2, VCP_RX (out), VCP_TX (in)

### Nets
3V3_LDO: C37.1 CN6.1 R45.1 SB6.1 U9.8(VDD)
3V6_LDO: C38.1 U9.5(VBAT)
5V: CN9.8
5V_SMPS_VBUS: CN1.2
GND: B1.2 B1.4 B2.7(MT) B2.8(MT) C36.2 C37.2 C38.2 C39.2 C40.2 C41.2 C42.2 C43.2 C44.1 C45.1 C46.1 C47.1 C48.1 C49.1 C50.1 C51.1 C52.1 C53.1 C54.1 CN1.3 CN8.8 LD4.2 LD5.2 LD6.2 LD7.2 R35.1 R37.1 R38.1 R40.1 U8.9(VSS) U9.7(VSS) U9.9(BS0) U9.10(BS1) U9.16(D2) U9.20(VLSS)
VDD: C45.2 C46.2 C47.2 CN1.1 CN6.2 CN9.1 L2.1 SB6.2 U8.6(VBAT) U8.8(3V3_LDO)
VREF+: C48.2 C49.2 L2.2 U8.7(VREF+)
ALERT_CC1: U8.38(PC6) ; port ALERT_CC1
ALERT_CC2: U8.39(PC7) ; port ALERT_CC2
ALERT_VBUS: U8.26(PC5) ; port ALERT_VBUS
CS_DISP: U8.20(PA3) U9.11(CS#)
D/C_DISP: U8.24(PA7) U9.13(D/C#)
DOOR_SENSE: U8.48(PC8) ; port DOOR_SENSE
EN_SMPS: U8.17(PA0) ; port EN_SMPS
ENCC1: U8.30(PB10) ; port ENCC1
ENCC2: U8.31(PB11) ; port ENCC2
I2C1_SCL: U8.60(PB6) ; port I2C1_SCL
I2C1_SDA: U8.61(PB7) ; port I2C1_SDA
JOY_DOWN: B2.3(DOWN) C52.2 U8.15(PC2)
JOY_LEFT: B2.1(LEFT) C51.2 U8.14(PC1)
JOY_RIGHT: B2.6(RIGHT) C53.2 U8.16(PC3)
JOY_SEL: B2.2(CENTER) C50.2 U8.13(PC0)
JOY_UP: B2.4(UP) C54.2 U8.25(PC4)
MCO: SB5.2 ; port MCO
NRST: B1.1 B1.3 C44.2 U8.12(PF2-NRST) ; port NRST
PA4: SB12.1 U8.21(PA4)
PA5: SB11.1 U8.22(PA5)
PA15: CN8.2 U8.47(PA15)
PB0: CN8.1 U8.27(PB0)
PB1: CN8.3 U8.28(PB1)
PB2: CN1.4 SB11.2 U8.29(PB2)
PB3: CN8.4 U8.57(PB3)
PB4: CN8.5 U8.58(PB4)
PB5: CN8.6 U8.59(PB5)
PB8: CN1.7 U8.62(PB8)
PB9: CN1.8 U8.63(PB9)
PB13: SB13.1 U8.33(PB13)
PB14: CN8.7 U8.34(PB14)
PC9: CN9.3 U8.49(PC9)
PC13: CN9.4 U8.3(PC13)
PC14: R36.1 U8.4(PC14-OSC32_IN)
PC15: R39.1 U8.5(PC15-OSC32_OUT)
PD0: CN1.5 SB13.2 SB14.1 U8.50(PD0)
PD1: CN9.5 SB14.2 U8.51(PD1)
PD2: CN1.6 SB12.2 SB15.1 U8.52(PD2)
PD3: CN9.6 SB15.2 U8.53(PD3)
PD4: CN9.7 U8.54(PD4)
PD5: R61.2 U8.55(PD5)
PD6: CN9.2 U8.56(PD6)
PD8: R33.2 U8.40(PD8)
PD9: R32.2 U8.41(PD9)
PF0: R41.1 SB5.1 U8.10(PF0-OSC_IN)
PF1: R44.1 U8.11(PF1-OSC_OUT)
RD_CC1: U8.32(PB12) ; port RD_CC1
RST_DISP: U8.23(PA6) U9.12(RES#)
SMPS_ON: U8.44(PA12) ; port SMPS_ON
SPI1_MOSI: U8.19(PA2) U9.15(D1)
SPI1_SCK: U8.18(PA1) U9.14(D0)
STLK_ON: U8.43(PA11) ; port STLK_ON
STLK_SWCLK: R37.2 U8.46(PA14-boot0) ; port STLK_SWCLK
STLK_SWDIO: U8.45(PA13) ; port STLK_SWDIO
USBPD1_CC1: U8.36(PA8) ; port USBPD1_CC1
USBPD1_CC2: U8.35(PB15) ; port USBPD1_CC2
VCP_RX: U8.1(PC11) ; port VCP_RX
VCP_TX: U8.64(PC10) ; port VCP_TX
NetB2_5: B2.5(COMMON) R45.2
NetC34_1: C34.1 U9.2(C2P)
NetC34_2: C34.2 U9.1(C2N)
NetC35_1: C35.1 U9.3(C1P)
NetC35_2: C35.2 U9.4(C1N)
NetC36_1: C36.1 U9.6(VCC) U9.19(VCC)
NetC39_1: C39.1 R36.2 X2.1
NetC40_1: C40.1 R39.2 X2.2
NetC41_1: C41.1 U9.18(VCOMH)
NetC42_1: C42.1 R41.2 X3.2(OSC2)
NetC43_1: C43.1 R44.2 X3.1(OSC1)
NetLD4_1: LD4.1 R32.1
NetLD5_1: LD5.1 R33.1
NetLD6_1: LD6.1 R52.1
NetLD7_1: LD7.1 R61.1
NetR35_2: R35.2 U8.37(PA9)
NetR38_2: R38.2 U8.42(PA10)
NetR40_2: R40.2 U9.17(IREF)
NetR52_2: R52.2 U8.2(PC12)

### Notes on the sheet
- (near U8) USBPD1_DBCC1(PA9) and USBPD1_DBCC2(PA10) to GND
- All SBs and test points on bottom side
- (near U9) OLED DISPLAY
- (near U8) PA3
- (near U8) PA1
- (near U8) PA2
- (near U8) PA0
- (near U8) PC0
- (near U8) PC1
- (near U8) PC2
- (near U8) PC3
- (near U8) PA6
- (near U8) PA7
- (near U8) PA8
- (near U8) PC4
- (near U8) PC5
- (near U8) PC6
- (near U8) PC7
- (near U8) PC8
- (near U8) PA11
- (near U8) PA12
- (near U8) PA13
- (near U8) PA9
- (near U8) PA10
- (near U8) PC10
- (near U8) PC11
- (near U8) PC12
- (near U8) PA14
- (near SB14) Dead battery mode enabled
- (near U8) PB6
- (near U8) PB7
- (near U8) PB10
- (near U8) PB11
- (near U8) PB12
- (near U8) PB15
- (near U8) PF2
- (near U8) U8 on bottom side
- (near CN6) IDD
- (near B1) RESET
- USER JOYSTICK
- CN8 and CN9 on bottom side
- /USBPD2_CC1
- /USBPD2_CC2
- /SPI2_MISO/ADC_IN10
- /I2C1_SCL/USART3_TX
- /I2C1_SDA/USART3_RX
- /DAC1_OUT1/ADC_IN4/SPI2_MOSI
- /DAC1_OUT2/ADC_IN5
- /SPI2_CLK

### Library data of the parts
B1 = MCD-01510: Microminiature SMT Top, 2N, N.O., IP67; Part_Type: Misc; Manufacturer_Part_Number: KMR721NG LFS; Manufacturer: C&K; Provided_By: SUBCO; Initial_Board_Reference: MB1378; Path: ws/MCD_ApplicationBoards/Lists/MCDPARTSdatabase; Item Type: Item
B2 = MCD-00132: Joystick, 4 dir, 1 OK; Part_Type: Misc; Manufacturer: XIEJIA Electronics; Provided_By: Subcon; Initial_Board_Reference: MB1262
C34 C35 C37 C38 = MCD-00010: Capacitor, MLCC, 1uF, 16V, X5R, 10%, 0603, T=0,8mm; Manufacturer_Part_Number: CC0603KRX5R7BB105; Manufacturer: YAGEO; Provided_By: Subcon; Initial_Board_Reference: MB1274
C36 C41 = MCD-01043: Capacitor, Tantalum, 4.7µF, 25V, 10%, 1206; Manufacturer_Part_Number: 293D475X9025A2TE3; Manufacturer: VISHAY; Provided_By: Subcon; Initial_Board_Reference: MB1378
C39 C40 = MCD-01374: Capacitor, MLCC, 5.6pF, 50V, NPO, 5%, 0402, T=0,5mm; Manufacturer_Part_Number: CC0402BRNPO9BN5R6; Manufacturer: YAGEO; Provided_By: SUBCO; Initial_Board_Reference: MB1363; Path: ws/MCD_ApplicationBoards/Lists/MCDPARTSdatabase; Item Type: Item
C42 C43 = MCD-00556: Capacitor, MLCC, 3.9pF, 50V, NPO, +-0.25pF, 0402, T=0,5mm; Manufacturer_Part_Number: CC0402CRNPO9BN3R9; Manufacturer: YAGEO; Provided_By: Subcon; Initial_Board_Reference: MB1331
C44-C46 C50-C54 = MCD-00102: Capacitor, MLCC, 100nF, 16V, X7R, 10%, 0402, T=0,5mm; Manufacturer_Part_Number: CC0402KRX7R7BB104; Manufacturer: YAGEO; Provided_By: Subcon; Initial_Board_Reference: MB1262
C47 = MCD-00097: Capacitor, MLCC, 4.7uF, 16V, X5R, 20%, 0603, T=0,8mm; Manufacturer_Part_Number: GRM188R61C475MAAJ; Manufacturer: MURATA; ECCN_US: EAR99; ECCN_EU: NEC; Provided_By: Subcon; Initial_Board_Reference: MB1262
C48 = MCD-00238: as C21 on sheet ST_LINK_V2_1
C49 = MCD-01007: Capacitor, MLCC, 10nF, 16V, X7R, 10%, 0603, T=0.8mm; Manufacturer_Part_Number: CC0603KRX7R7BB103; Manufacturer: YAGEO; Provided_By: Subcon; Initial_Board_Reference: MB1379
CN1 = MCD-01382: Header, 8x1, 2.54mm, RA, through-hole; Part_Type: Connector; Manufacturer_Part_Number: TSW_108_08_G_S_RA; Manufacturer: SAMTECH; Provided_By: Subcon; Initial_Board_Reference: MB1378
CN6 = MCD-00314: Header, 2x1, 2.54mm, VR, TH, Height 6mm/3mm; Part_Type: Connector; Manufacturer_Part_Number: PHFS25-11-02-G0B115-T-1; Manufacturer: JIUBABA; Provided_By: Subcon; Initial_Board_Reference: MB1311
CN8 CN9 = MCD-00239: Header, 8x1, 2,54mm, VR, TH, Height 5.84mm/2.54mm; Part_Type: Connector; Manufacturer_Part_Number: TSW-108-07-x-S; Manufacturer: SAMTEC; Provided_By: Subcon; Initial_Board_Reference: MB1319
L2 = MCD-00552: Bead,600R,350mA,0603; Part_Type: Inductor; Manufacturer_Part_Number: FCM1608KF-601T03; Manufacturer: TAI-TECH; Provided_By: Subcon
LD4 LD5 = MCD-01378: LED ORANGE, 1.9V, 20mA, side; Part_Type: Display; Manufacturer_Part_Number: HSML-C120; Manufacturer: BROADCOM LIMITED; Provided_By: Subcon; Initial_Board_Reference: MB1378
LD6 LD7 = MCD-01376: LED GREEN, 2.2V, 20mA, side; Part_Type: Display; Manufacturer_Part_Number: HSMG-C120; Manufacturer: BROADCOM LIMITED; Provided_By: Subcon; Initial_Board_Reference: MB1378; Remark: Footprint to be created
R32 R33 = MCD-00354: Resistor,470R,0603,1%,1/10W; Manufacturer_Part_Number: RC0603FR-07470RL; Manufacturer: YAGEO; Provided_By: Subcon
R35 R36 R38 R39 R41 R44 = MCD-00056: as R57 on sheet USB_typeC_CurrentSensing
R37 = MCD-00223: as R59 on sheet USB_typeC_CurrentSensing
R40 = MCD-00506: Resistor,620K,0603,1%,1/10W; Manufacturer_Part_Number: RC0603FR-07620KL; Manufacturer: YAGEO; Provided_By: Subcon
R45 = MCD-00224: as R18 on sheet ST_LINK_V2_1
R52 R61 = MCD-00342: Resistor,180R,0603,1%,1/10W; Manufacturer_Part_Number: RC0603FR-07180RL; Manufacturer: YAGEO; Provided_By: SUBCO; Initial_Board_Reference: MBxxxx; Path: ws/MCD_ApplicationBoards/Lists/MCDPARTSdatabase; Item Type: Item
SB5 SB6 = MCD-00071: as SB1 on sheet ST_LINK_V2_1
SB11-SB15 = MCD-00072: as SB7 on sheet USB_typeC_CurrentSensing
U8 = MCD-01047: ARM® Cortex®-M0+ 32-bit MCU, 128 KB Flash, 32 KB RAM, / 4x USART, timers, ADC, DAC, comm. I/F, 1.65-3.6V; Part_Type: IC; Manufacturer: STMICROELECTRONICS; ECCN_US: 3A991A2; ECCN_EU: NEC; Provided_By: STM; Initial_Board_Reference: MB1378
U9 = MCD-01511: 128*64 20-pin OLED display driver SSD1306BZ Parallel or SPI interface; Provided_By: SUBCO; Initial_Board_Reference: MB1378; Path: ws/MCD_ApplicationBoards/Lists/MCDPARTSdatabase; Item Type: Item
X2 = MCD-00091: Crystal 32.768kHz, 6pF, -+20PPM, R=50K, SMD; Part_Type: Crystal_Osc; Manufacturer_Part_Number: NX3215SA 32.768KHz EXS00A-MU00525; Manufacturer: NDK; ECCN_US: EAR99; ECCN_EU: NEC; Provided_By: STM; Initial_Board_Reference: MB1274
X3 = MCD-00092: Crystal 8Mhz, 8pF, -+50PPM, SMD; Part_Type: Crystal_Osc; Manufacturer_Part_Number: NX3225GD 8MHz EXS00A-CG04874; Manufacturer: NDK; ECCN_US: EAR99; ECCN_EU: NEC; Provided_By: STM; Initial_Board_Reference: MB1274

## Sheet Power_Supply.SchDoc: Power Supply
size A4; Date: Not used; ApprovedBy: Not used; CheckedBy: Not used; Author: Not used; CompanyName: STMicroelectronics; DrawnBy: Not used; Engineer: Not used; Organization: Not used; Address1: Not used; Address2: Not used; Address3: Not used; Address4: Not used; DocumentNumber: 5; Revision: Not used; SheetNumber: 5; SheetTotal: 7
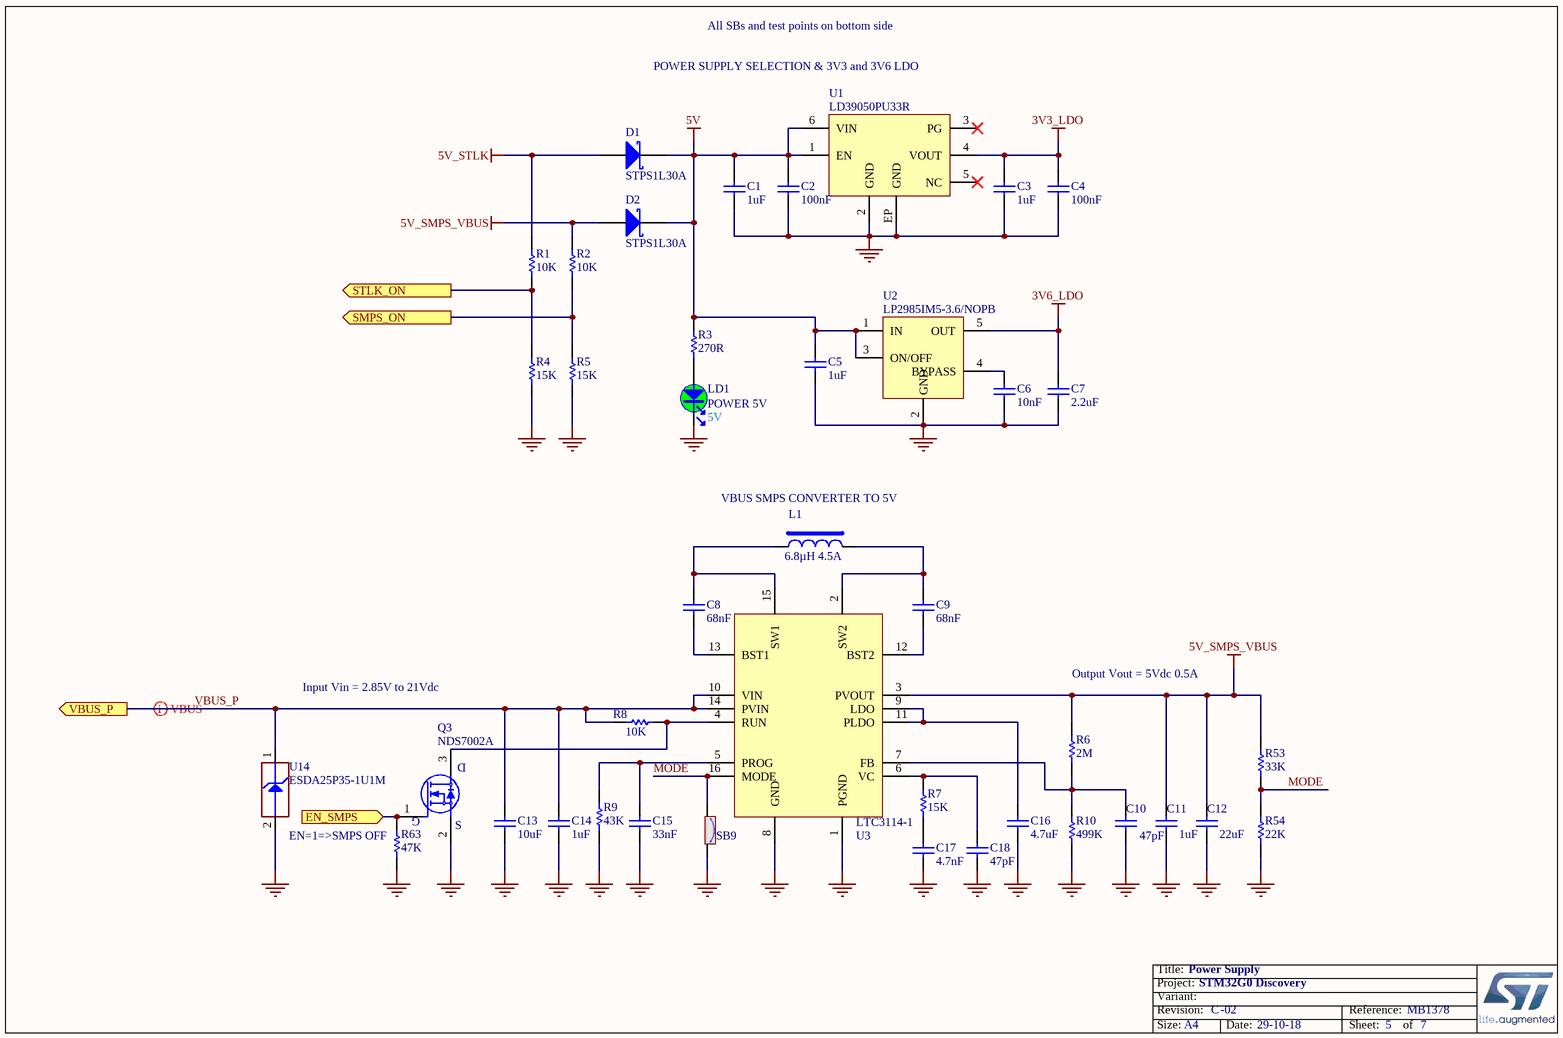
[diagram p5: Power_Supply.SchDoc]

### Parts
C1  value 1uF  [C0603]
C2  value 100nF  [C0402]
C3  value 1uF  [C0603]
C4  value 100nF  [C0402]
C5  value 1uF  [C0603]
C6  value 10nF  [C0603]
C7  value 2.2uF  [C0603]
C8  value 68nF  [C0603]  (hidden comment: ​Footprint available C0603)
C9  value 68nF  [C0603]  (hidden comment: ​Footprint available C0603)
C10  value 47pF  [C1206_H1P25]  (hidden comment: ​Footprint available)
C11  value 1uF  [C0603]
C12  value 22uF  [C1210]
C13  value 10uF  [C1210]  (hidden comment: ​Footprint available C1210)
C14  value 1uF  [C0603]  (hidden comment: Footprint available C0603)
C15  value 33nF  [C0603]  (hidden comment: ​​Footprint available C0603)
C16  value 4.7uF  [C0603]
C17  value 4.7nF  [C0603]  (hidden comment: ​Footprint available C0603)
C18  value 47pF  [C1206_H1P25]  (hidden comment: ​Footprint available)
D1  value STPS1L30A  [DIO_SMA_1A_2K]  (hidden comment: STPS1L40M)
D2  value STPS1L30A  [DIO_SMA_1A_2K]  (hidden comment: STPS1L40M)
L1  value 6.8µH 4.5A  [IND_WURTH_WE-LHMI-8040]  (hidden comment: INDUCTOR_POWER)
LD1  value POWER 5V  [LED_BROADCOM-HSMG-C120]  (hidden comment: LED_green)
Q3  value NDS7002A  [ICC_SOT23-3L_H1P12]  (hidden comment: MOSFET_N-CHANNEL)
R1  value 10K  [R0603]
R2  value 10K  [R0603]
R3  value 270R  [R0603]  (hidden comment: Resistor)
R4  value 15K  [R0603]
R5  value 15K  [R0603]
R6  value 2M  [R0603]  (hidden comment: Resistor)
R7  value 15K  [R0603]
R8  value 10K  [R0603]
R9  value 43K  [R0603]
R10  value 499K  [R0603]  (hidden comment: ​Footprint R0603)
R53  value 33K  [R0603]  (hidden comment: Resistor)
R54  value 22K  [R0603]  (hidden comment: Resistor)
R63  value 47K  [R0603]  (hidden comment: Resistor)
SB9  (no value)  [SOLDER-BRIDGE_R0603-0R]
U1  value LD39050PU33R  [ICC_DFN6-EPAD_3X3_P095]
U2  LP2985IM5-3.6/NOPB  [REG_SOT23-5L]
U3  value LTC3114-1  [TSOP65P640X110_HS-17N]  (hidden comment: ​Footprint TSOP65P640X110_HS-17N)
U14  value ESDA25P35-1U1M  [ESD_QFN1610_2N_1K_2A]  (hidden comment: ESD-TRANSIL)

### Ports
EN_SMPS (in), SMPS_ON (out), STLK_ON (out), VBUS_P (out)

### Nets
3V3_LDO: C3.1 C4.2 U1.4(VOUT)
3V6_LDO: C7.2 U2.5(OUT)
5V: C1.2 C2.2 C5.1 D1.2(K) D2.2(K) R3.2 U1.1(EN) U1.6(VIN) U2.1(IN) U2.3(ON/OFF)
5V_SMPS_VBUS: C11.2 C12.2 D2.1(A) R2.2 R6.2 R53.2 U3.3(PVOUT)
5V_STLK: D1.1(A) R1.2
GND: C1.1 C2.1 C3.2 C4.1 C5.2 C6.1 C7.1 C10.1 C11.1 C12.1 C13.1 C14.1 C15.1 C16.1 C17.1 C18.1 LD1.2 Q3.2(S) R4.1 R5.1 R9.1 R10.1 R54.1 R63.1 SB9.2 U1.2(GND) U1.EP(GND) U2.2(GND) U3.1(PGND) U3.8(GND) U14.2(GND)
EN_SMPS: Q3.1(G) R63.2 ; port EN_SMPS
MODE: R53.1 R54.2 SB9.1 U3.16(MODE)
SMPS_ON: R2.1 R5.2 ; port SMPS_ON
STLK_ON: R1.1 R4.2 ; port STLK_ON
VBUS_P: C13.2 C14.2 R8.2 U3.10(VIN) U3.14(PVIN) U14.1(IO1) ; port VBUS_P
NetC6_2: C6.2 U2.4(BYPASS)
NetC8_1: C8.1 U3.13(BST1)
NetC8_2: C8.2 L1.1 U3.15(SW1)
NetC9_1: C9.1 U3.12(BST2)
NetC9_2: C9.2 L1.2 U3.2(SW2)
NetC10_2: C10.2 R6.1 R10.2 U3.7(FB)
NetC15_2: C15.2 R9.2 U3.5(PROG)
NetC16_2: C16.2 U3.9(LDO) U3.11(PLDO)
NetC17_2: C17.2 R7.1
NetC18_2: C18.2 R7.2 U3.6(VC)
NetLD1_1: LD1.1 R3.1
NetQ3_3: Q3.3(D) R8.1 U3.4(RUN)

Not connected (* = marked no-connect by the designer): U1 3(PG)* 5(NC)*

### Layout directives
differential pair: VBUS_P

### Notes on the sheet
- All SBs and test points on bottom side
- POWER SUPPLY SELECTION & 3V3 and 3V6 LDO
- (near LD1) 5V
- (near L1) VBUS SMPS CONVERTER TO 5V
- Input Vin = 2.85V to 21Vdc
- Output Vout = 5Vdc 0.5A
- EN=1=>SMPS OFF

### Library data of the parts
C1 C3 C5 C11 = MCD-00010: as C34 on sheet MCU_Display
C2 C4 = MCD-00102: as C44 on sheet MCU_Display
C6 = MCD-01007: as C49 on sheet MCU_Display
C7 = MCD-00551: Capacitor, MLCC, 2.2uF, 10V, X5R, 10%, 0603, T=0,8mm; Manufacturer_Part_Number: C0603C225K8PACTU; Manufacturer: KEMET; Alternate_Manufacturer_Part_Number: CC0603KRX5R6BB225; Alternate_Manufacturer: YAGEO; Provided_By: Subcon
C8 C9 = MCD-01050: Capacitor, X7R, 68nF, 50V, 10%, 0603, T=1mm; Manufacturer_Part_Number: 06035C683KAT2A; Manufacturer: AVX; Provided_By: Subcon; Initial_Board_Reference: MB1378
C10 C18 = MCD-01048: Capacitor, NP0, 47pF, 50V, C0G, 5%, 1206, T=1.25mm; Manufacturer_Part_Number: 1206CG470J500NT; Manufacturer: Fenghua; Provided_By: Subcon; Initial_Board_Reference: MB1378
C12 = MCD-00614: Capacitor, MLCC, 22uF, 16V, 1210, X7R, 20%, T=2,5mm, ESR 2mohm@410KHz; Manufacturer_Part_Number: GCM32ER71C226ME19; Manufacturer: MURATA; Provided_By: Subcon; Initial_Board_Reference: MB1331
C13 = MCD-01056: Capacitor, X7R, 10µF, 50V, 20%, 1210, T=2.5mm; Manufacturer_Part_Number: C3225X7R1H106M250AC; Manufacturer: TDK; Provided_By: Subcon; Initial_Board_Reference: MB1378
C14 = MCD-01053: Capacitor, C-series, X5R, 1µF, 50V, 10%, 0603, T=0.8mm; Manufacturer_Part_Number: C1608X5R1H105K080AB; Manufacturer: TDK; Provided_By: Subcon; Initial_Board_Reference: MB1378
C15 = MCD-01052: Capacitor, X7R, 33nF, 50V, 5%, 0603, T=1.25mm; Manufacturer_Part_Number: 06035C333JAT2A; Manufacturer: AVX; Provided_By: Subcon; Initial_Board_Reference: MB1378
C16 = MCD-00009: Capacitor, MLCC, 4.7uF, 16V, X5R, 10%, 0603, T=0.8mm; Manufacturer_Part_Number: CC0603KRX5R7BB475; Manufacturer: YAGEO; Provided_By: subcon; Initial_Board_Reference: MB1274
C17 = MCD-01049: Capacitor, MLCC, 4.7nF, 100V, X7R, 10%, 0603, T=1mm; Manufacturer_Part_Number: 06031C472K4T2A; Manufacturer: AVX; Provided_By: Subcon; Initial_Board_Reference: MB1378
D1 D2 = MCD-01059: LOW DROP POWER SCHOTTKY RECTIFIER 1A 30V VF=0.3V; Part_Type: Diode; Manufacturer: STMICROELECTRONICS; Provided_By: STM; Initial_Board_Reference: MB1378
L1 = MCD-01372: Inductor 6.8µH +/-20% Isat= 13.5A DCR=33.40 mOhm; Manufacturer_Part_Number: 744 373 580 68; Manufacturer: WURTH ELEKTRONIK; Provided_By: Subcon; Initial_Board_Reference: MB1378
LD1 = MCD-01376: as LD6 on sheet MCU_Display
Q3 = MCD-01518: MOSFET, Single N-Channel , Vgs(th): 2.5V, Id: 280mA, Vds(max): 60V, Vgs(max): +/-20V, Rdson:3 ohm@Vgs=5V; Part_Type: IC; Manufacturer: ON SEMICONDUCTOR; Alternate_Manufacturer: FAIRCHILD; Provided_By: SUBCO; Initial_Board_Reference: MB1428; Path: ws/MCD_ApplicationBoards/Lists/MCDPARTSdatabase; Item Type: Item
R1 R2 R8 = MCD-00220: Resistor,10K,0603,1%,1/10W; Manufacturer_Part_Number: RC0603FR-0710KL; Manufacturer: YAGEO; Provided_By: Subcon; Initial_Board_Reference: MB1319
R3 = MCD-00442: Resistor,270R,0603,1%,1/10W; Manufacturer_Part_Number: RC0603FR-07270RL; Manufacturer: YAGEO; Provided_By: SUBCO; Initial_Board_Reference: MBxxxx; Path: ws/MCD_ApplicationBoards/Lists/MCDPARTSdatabase; Item Type: Item
R4 R5 R7 = MCD-00341: Resistor,15K,0603,1%,1/10W; Manufacturer_Part_Number: RC0603FR-0715KL; Manufacturer: YAGEO; Provided_By: Subcon
R6 = MCD-00426: Resistor,2M,0603,1%,1/10W; Manufacturer_Part_Number: RC0603FR-072ML; Manufacturer: YAGEO; Provided_By: Subcon
R9 = MCD-00478: Resistor,43K,0603,1%,1/10W; Manufacturer_Part_Number: RC0603FR-0743KL; Manufacturer: YAGEO; Provided_By: Subcon
R10 = MCD-01032: Resistor 499K 1% 75V 0.063W; Manufacturer_Part_Number: MC0603SAF4993T5E; Manufacturer: MULTICOMP; Provided_By: Subcon; Initial_Board_Reference: MB1378
R53 = MCD-00259: Resistor,33K,0603,1%,1/10W; Manufacturer_Part_Number: RC0603FR-0733KL; Manufacturer: YAGEO; Provided_By: Subcon; Initial_Board_Reference: MB1319
R54 = MCD-00430: as R43 on sheet ST_LINK_V2_1
R63 = MCD-00222: Resistor,47K,0603,1%,1/10W; Manufacturer_Part_Number: RC0603FR-0747KL; Manufacturer: YAGEO; Provided_By: SUBCO; Initial_Board_Reference: MB1319; Path: ws/MCD_ApplicationBoards/Lists/MCDPARTSdatabase; Item Type: Item
SB9 = MCD-00071: as SB1 on sheet ST_LINK_V2_1
U1 = MCD-00215: Low quiescent current and low noise voltage regulators; Part_Type: IC; Manufacturer: STMICROELECTRONICS; ECCN_US: EAR99; ECCN_EU: NEC; Provided_By: Subcon; Initial_Board_Reference: MB1319
U2 = MCD-01030: LDO VOLTAGE REGULATOR, 3.6V, 150mA, 5-SOT-23, FULL REEL; Part_Type: IC; Manufacturer: TEXAS INSTRUMENTS; Provided_By: Subcon; Initial_Board_Reference: MB1378; Remark: Footprint REG_SOT23-5L
U3 = MCD-01016: Integrated Circuit 40V, 1A Synchronous Buck-Boost DC/DC Converter with Programmable Output Current; Part_Type: IC; Manufacturer: LINEAR TECHNOLOGY; ECCN_US: EAR99; ECCN_EU: NEC; Provided_By: Subcon; Initial_Board_Reference: MB1378
U14 = MCD-01207: High power Transient voltage suppressor:25V/35A EOS and ESD transients protection.; Part_Type: Diode; Manufacturer: STMICROELECTRONICS; Provided_By: Subcon; Initial_Board_Reference: MB1372

## Sheet Mechanical.SchDoc: Mechanical
size A4; Date: Not used; ApprovedBy: Not used; CheckedBy: Not used; Author: Not used; CompanyName: STMicroelectronics; DrawnBy: Not used; Engineer: Not used; Organization: Not used; Address1: Not used; Address2: Not used; Address3: Not used; Address4: Not used; DocumentNumber: 7; Revision: Not used; SheetNumber: 7; SheetTotal: 7
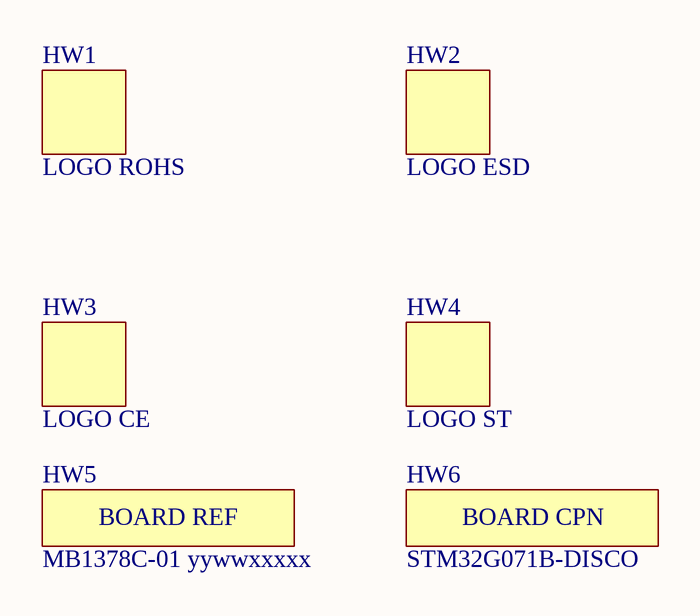
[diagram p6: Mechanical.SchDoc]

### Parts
HW1  value LOGO ROHS  [LOGO_ROHS]  (hidden comment: Logo)  (no BOM)
HW2  value LOGO ESD  [LOGO_MAIN]  (hidden comment: Logo)  (no BOM)
HW3  value LOGO CE  [LOGO_CE]  (hidden comment: Logo)  (no BOM)
HW4  value LOGO ST  [LOGO_ST]  (hidden comment: Logo)  (no BOM)
HW5  value MB1378C-01 yywwxxxxx  (hidden comment: STICKER_BOARD_REF)  (mechanical)
HW6  value STM32G071B-DISCO  (hidden comment: STICKER_BOARD_CPN)  (mechanical)

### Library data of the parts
HW1 = MCD-00628: "ROHS" logo footprint for PCB; Part_Type: Mechanical; Initial_Board_Reference: MB1331
HW2 = MCD-00627: "Hand" ESD logo footprint for PCB; Part_Type: Mechanical; Initial_Board_Reference: MB1331
HW3 = MCD-00626: "CE" logo footprint for PCB; Part_Type: Mechanical; Initial_Board_Reference: MB1331
HW4 = MCD-00625: "STMicroelectronics" logo footprint for PCB; Part_Type: Mechanical; Initial_Board_Reference: MB1331
HW5 = MCD-00235: Sticker to mention board reference + serial number; Part_Type: Mechanical; Provided_By: Subcon; Initial_Board_Reference: MB1319
HW6 = MCD-00547: Sticker to mention board CPN code; Part_Type: Mechanical; Provided_By: Subcon; Initial_Board_Reference: MB1319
